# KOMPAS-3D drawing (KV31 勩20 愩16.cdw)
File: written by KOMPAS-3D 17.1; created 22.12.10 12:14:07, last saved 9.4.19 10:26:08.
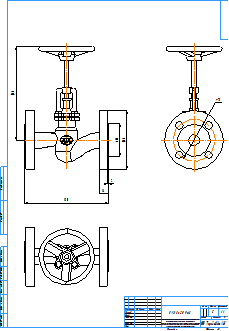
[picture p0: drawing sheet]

Title block, sheet 1: name: KV31 Ду20 Ру16; material: Внимание! Данный продукт является объектом авторского права ООО «Торговый Дом АДЛ». / Запрещается изменение, копирование, распространение / (в том числе путем копирования на другие сайты и ресурсы в Интернете) / или любое иное использование информации и объектов без предварительного / согласия правообладателя (ООО «Торговый Дом АДЛ»).; mass: 5; scale: 1:1; sheets: 1; organisation: ООО "Торговый дом АДЛ"; sheet format: A2; stored path: \\adlc.lan\data\АДЛ_ПКД\3D-модели\ADL production\Вентили ГРАНВЕНТ\KV31\KOMPAS 2D\KV31 Ду20.cdw

Views: Спереди 1, Проекционный вид 2, Проекционный вид 3
Dimensions and other numbers on the sheet: 56; 105; 150; 2; 16; 75; 166; 1:1; 1; 5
